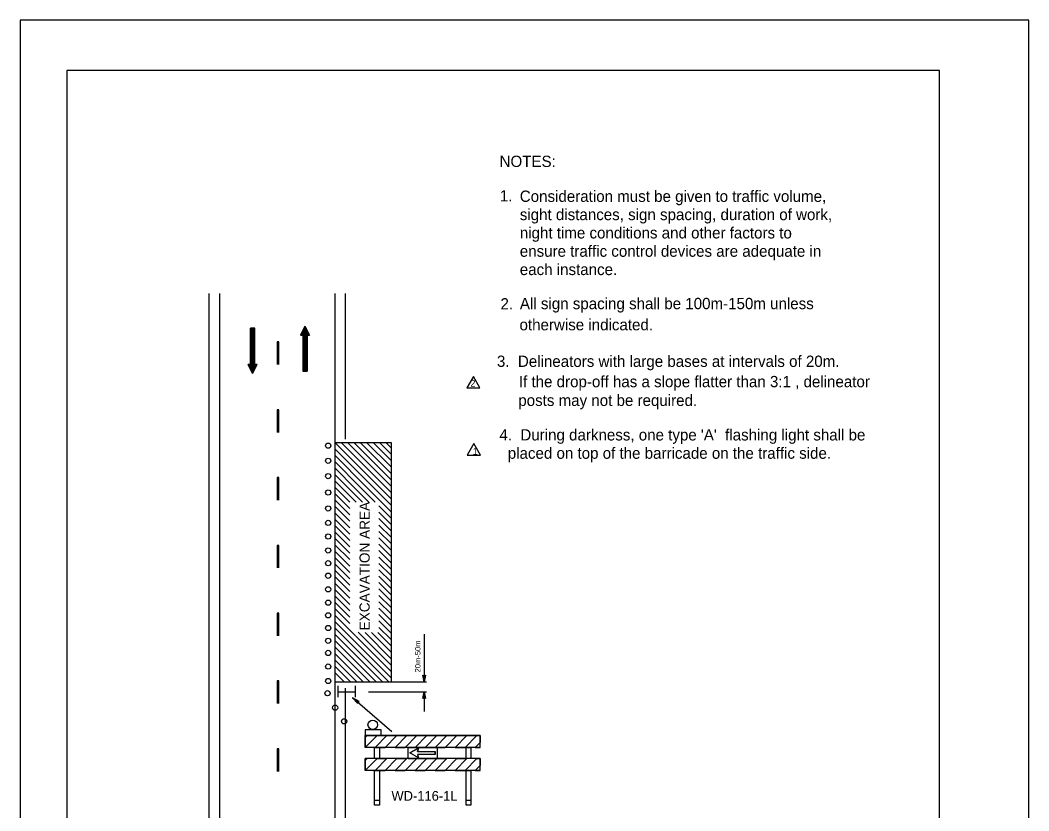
# Model space of a CAD drawing. Extents: x 1387 to 1603, y 134 to 413.
# Drawn here: x 1386.9 to 1602.9, y 243.5 to 412.8 of the extents above; entities that cross this region are included whole.
import ezdxf

# ---------------------------------------------------------------- set-up
doc = ezdxf.new("R2010")
doc.units = 0
for name, color, linetype in [('Level 1', 7, 'Continuous'), ('Level 10', 7, 'Continuous'), ('Level 2', 7, 'Continuous'), ('Level 3', 7, 'Continuous'), ('Level 5', 7, 'Continuous'), ('Level 60', 7, 'Continuous')]:
    doc.layers.add(name, color=color, linetype=linetype)

msp = doc.modelspace()

# ---------------------------------------------------------------- linework, layer by layer
at = {"layer": 'Level 1'}
msp.add_lwpolyline([(1484.02, 322.11), (1482.6, 319.64), (1485.43, 319.64)], close=True, dxfattribs=at)
msp.add_lwpolyline([(1458.06, 267.67), (1459.15, 266.47), (1459.11, 266.85), (1459.48, 266.89), (1458.06, 267.67), (1458.45, 267.37), (1459.04, 266.72), (1459.01, 266.92), (1459.21, 266.94), (1458.45, 267.37), (1458.83, 267.06), (1458.93, 266.94), (1458.93, 266.98), (1458.97, 266.99), (1458.83, 267.06), (1458.93, 266.98)], dxfattribs=at)
at = {"layer": 'Level 10'}
for p, q in [((1427.31, 354.27), (1427.31, 172.77)), ((1429.55, 354.27), (1429.55, 172.77)), ((1454.23, 354.27), (1454.23, 172.77)), ((1456.49, 354.27), (1456.49, 323.04)), ((1436.18, 339.07), (1436.18, 346.81)), ((1437.15, 346.81), (1436.18, 346.81)), ((1436.18, 338.1), (1436.18, 346.81)), ((1436.3, 337.86), (1436.3, 346.81)), ((1436.42, 337.62), (1436.42, 346.81)), ((1436.54, 337.38), (1436.54, 346.81)), ((1436.66, 337.14), (1436.66, 346.81)), ((1436.78, 337.38), (1436.78, 346.81)), ((1436.9, 337.62), (1436.9, 346.81)), ((1437.03, 337.86), (1437.03, 346.81)), ((1437.15, 339.07), (1437.15, 346.81)), ((1437.15, 338.1), (1437.15, 346.81)), ((1447.86, 347.27), (1446.89, 345.33)), ((1447.14, 345.82), (1447.14, 345.33)), ((1447.26, 346.06), (1447.26, 345.33)), ((1447.38, 346.3), (1447.38, 337.59)), ((1447.5, 346.54), (1447.5, 337.59)), ((1447.62, 346.79), (1447.62, 337.59)), ((1447.74, 347.03), (1447.74, 337.59)), ((1447.86, 347.27), (1447.86, 337.59)), ((1447.86, 347.27), (1448.83, 345.33)), ((1447.98, 347.03), (1447.98, 337.59)), ((1448.1, 346.79), (1448.1, 337.59)), ((1448.22, 346.54), (1448.22, 337.59)), ((1448.35, 346.3), (1448.35, 337.59)), ((1448.47, 346.06), (1448.47, 345.33)), ((1448.59, 345.82), (1448.59, 345.33)), ((1446.89, 345.33), (1447.38, 345.33)), ((1447.02, 345.58), (1447.02, 345.33)), ((1447.38, 345.33), (1447.38, 337.59)), ((1448.35, 345.33), (1448.35, 337.59)), ((1448.35, 345.33), (1448.83, 345.33)), ((1448.71, 345.58), (1448.71, 345.33)), ((1436.66, 337.14), (1435.69, 339.07)), ((1436.18, 339.07), (1435.69, 339.07)), ((1435.82, 338.83), (1435.82, 339.07)), ((1435.94, 338.59), (1435.94, 339.07)), ((1436.06, 338.35), (1436.06, 339.07)), ((1436.66, 337.14), (1437.63, 339.07)), ((1437.63, 339.07), (1437.15, 339.07)), ((1437.27, 338.35), (1437.27, 339.07)), ((1437.39, 338.59), (1437.39, 339.07)), ((1437.51, 338.83), (1437.51, 339.07)), ((1447.38, 337.59), (1448.35, 337.59)), ((1454.23, 322.35), (1466.32, 322.35)), ((1454.23, 322.35), (1466.32, 310.26)), ((1454.23, 322.35), (1466.32, 322.35)), ((1455.6, 322.35), (1466.32, 311.62)), ((1456.97, 322.35), (1466.32, 312.99)), ((1458.34, 322.35), (1466.32, 314.36)), ((1459.7, 322.35), (1466.32, 315.73)), ((1461.07, 322.35), (1466.32, 317.1)), ((1462.44, 322.35), (1466.32, 318.47)), ((1463.81, 322.35), (1466.32, 319.83)), ((1465.18, 322.35), (1466.32, 321.2)), ((1466.32, 322.35), (1466.32, 271.07)), ((1454.23, 320.98), (1466.32, 308.89)), ((1454.23, 319.61), (1460.98, 312.86)), ((1454.23, 318.25), (1459.61, 312.86)), ((1454.23, 316.88), (1458.67, 312.44)), ((1454.23, 315.51), (1458.67, 311.07)), ((1454.23, 314.14), (1458.81, 309.56)), ((1454.23, 312.77), (1457.44, 309.56)), ((1454.23, 311.4), (1457.44, 308.19)), ((1457.98, 311.75), (1460.19, 309.55)), ((1458.67, 312.44), (1461.55, 309.56)), ((1459.61, 312.86), (1462.91, 309.56)), ((1460.98, 312.86), (1466.32, 307.52)), ((1454.23, 310.04), (1457.44, 306.83)), ((1454.23, 308.67), (1457.44, 305.46)), ((1454.23, 307.3), (1457.44, 304.09)), ((1463.71, 308.76), (1466.32, 306.15)), ((1463.71, 307.4), (1466.32, 304.78)), ((1454.23, 305.93), (1457.44, 302.72)), ((1454.23, 304.56), (1457.44, 301.35)), ((1463.71, 306.03), (1466.32, 303.41)), ((1463.71, 304.66), (1466.32, 302.05)), ((1454.23, 303.19), (1457.44, 299.99)), ((1463.71, 303.29), (1466.32, 300.68)), ((1454.23, 301.82), (1457.44, 298.62)), ((1454.23, 300.46), (1457.44, 297.25)), ((1463.71, 301.92), (1466.32, 299.31)), ((1463.71, 300.55), (1466.32, 297.94)), ((1454.23, 299.09), (1454.24, 299.08)), ((1454.23, 299.09), (1457.44, 295.88)), ((1463.71, 299.19), (1466.32, 296.57)), ((1454.23, 297.72), (1457.44, 294.51)), ((1454.23, 296.35), (1457.44, 293.14)), ((1463.71, 297.82), (1466.32, 295.2)), ((1463.71, 296.45), (1466.32, 293.83)), ((1454.23, 294.98), (1457.44, 291.77)), ((1463.71, 295.08), (1466.32, 292.47)), ((1454.23, 293.62), (1457.44, 290.41)), ((1454.23, 292.25), (1457.44, 289.04)), ((1463.71, 293.71), (1466.32, 291.1)), ((1463.71, 292.34), (1466.32, 289.73)), ((1454.23, 290.88), (1457.44, 287.67)), ((1454.23, 289.51), (1457.44, 286.3)), ((1463.71, 290.98), (1466.32, 288.36)), ((1463.71, 289.61), (1466.32, 286.99)), ((1454.23, 288.14), (1457.44, 284.93)), ((1463.71, 288.24), (1466.32, 285.62)), ((1454.23, 286.77), (1457.44, 283.56)), ((1454.23, 285.4), (1457.44, 282.19)), ((1463.71, 286.87), (1466.32, 284.26)), ((1463.71, 285.5), (1466.32, 282.89)), ((1454.23, 284.04), (1458.67, 279.6)), ((1463.71, 284.13), (1466.32, 281.52)), ((1454.23, 282.67), (1458.67, 278.23)), ((1454.23, 281.3), (1464.46, 271.07)), ((1457.46, 282.18), (1458.67, 280.97)), ((1458.74, 280.9), (1466.32, 273.31)), ((1459.28, 281.72), (1466.32, 274.68)), ((1460.73, 281.64), (1466.32, 276.05)), ((1462.1, 281.64), (1466.32, 277.41)), ((1463.47, 281.64), (1466.32, 278.78)), ((1463.71, 282.76), (1466.32, 280.15)), ((1473.39, 281.27), (1473.39, 271.07)), ((1454.23, 279.93), (1463.09, 271.07)), ((1458.68, 279.59), (1466.32, 271.94)), ((1454.23, 278.56), (1461.72, 271.07)), ((1454.23, 277.19), (1460.36, 271.07)), ((1458.66, 278.24), (1465.83, 271.07)), ((1454.23, 275.82), (1458.99, 271.07)), ((1454.23, 274.46), (1457.62, 271.07)), ((1454.23, 273.09), (1456.25, 271.07)), ((1454.23, 271.07), (1466.32, 271.07)), ((1454.99, 267.79), (1454.99, 270.26)), ((1458.66, 267.79), (1458.66, 270.26)), ((1466.32, 271.07), (1473.87, 271.07)), ((1454.99, 268.98), (1458.66, 268.98)), ((1456.49, 269.76), (1456.49, 172.77)), ((1461.5, 268.98), (1465.17, 268.98)), ((1465.17, 268.98), (1473.87, 268.98)), ((1473.39, 268.98), (1473.39, 264.75)), ((1466.46, 260.38), (1458.06, 267.67))]:
    msp.add_line(p, q, dxfattribs=at)
for points in [[(1473.39, 271.07), (1473.09, 272.52), (1473.39, 272.28), (1473.69, 272.52)], [(1473.39, 268.98), (1473.69, 267.53), (1473.39, 267.77), (1473.09, 267.53)], [(1460.76, 259.57), (1464.15, 259.57), (1464.15, 260.8), (1460.76, 260.8)]]:
    msp.add_lwpolyline(points, close=True, dxfattribs=at)
for centre, radius in [((1452.85, 321.65), 0.558), ((1452.85, 318.42), 0.558), ((1452.85, 315.14), 0.558), ((1452.85, 311.63), 0.558), ((1452.85, 308.22), 0.558), ((1452.85, 305.12), 0.558), ((1452.85, 302.21), 0.558), ((1452.85, 299.23), 0.558), ((1452.85, 296.48), 0.558), ((1452.85, 293.81), 0.558), ((1452.85, 290.9), 0.558), ((1452.85, 288.05), 0.558), ((1452.85, 285.34), 0.558), ((1452.85, 282.61), 0.558), ((1452.85, 279.88), 0.558), ((1452.85, 277.28), 0.558), ((1452.85, 274.36), 0.558), ((1452.85, 271.26), 0.558), ((1452.71, 268.66), 0.558), ((1454.31, 265.56), 0.558), ((1456.26, 262.64), 0.558), ((1462.38, 261.9), 1.02)]:
    msp.add_circle(centre, radius, dxfattribs=at)
at = {"layer": 'Level 2'}
for p, q in [((1441.94, 343.86), (1441.94, 339.02)), ((1442.24, 343.86), (1441.94, 343.86)), ((1442.24, 339.02), (1442.24, 343.86)), ((1441.94, 329.34), (1441.94, 324.5)), ((1442.24, 329.34), (1441.94, 329.34)), ((1442.24, 324.5), (1442.24, 329.34)), ((1441.94, 314.83), (1441.94, 309.99)), ((1442.24, 314.83), (1441.94, 314.83)), ((1442.24, 309.99), (1442.24, 314.83)), ((1441.94, 300.31), (1441.94, 295.48)), ((1442.24, 300.31), (1441.94, 300.31)), ((1442.24, 295.48), (1442.24, 300.31)), ((1441.94, 285.8), (1441.94, 280.96)), ((1442.24, 285.8), (1441.94, 285.8)), ((1442.24, 280.96), (1442.24, 285.8)), ((1441.94, 271.29), (1441.94, 266.45)), ((1442.24, 271.29), (1441.94, 271.29)), ((1442.24, 266.45), (1442.24, 271.29)), ((1460.65, 271.64), (1460.65, 271.64)), ((1441.94, 256.77), (1441.94, 251.93)), ((1442.24, 256.77), (1441.94, 256.77)), ((1442.24, 251.93), (1442.24, 256.77))]:
    msp.add_line(p, q, dxfattribs=at)
at = {"layer": 'Level 3'}
msp.add_line((1460.97, 271.66), (1460.97, 271.66), dxfattribs=at)
at = {"layer": 'Level 5'}
for p, q in [((1485.37, 259.57), (1460.76, 259.57)), ((1460.76, 257.05), (1460.76, 259.57)), ((1460.76, 259.57), (1485.37, 259.57)), ((1462.78, 259.57), (1463.29, 259.57)), ((1481.34, 259.57), (1480.33, 259.57)), ((1485.37, 257.05), (1485.37, 259.57)), ((1485.37, 257.05), (1460.76, 257.05)), ((1462.78, 257), (1462.78, 257.05)), ((1482.35, 257), (1482.35, 257.05)), ((1469.94, 257.02), (1476.15, 257.02)), ((1469.94, 257.02), (1476.15, 257.02)), ((1469.94, 254.7), (1469.94, 257.02)), ((1469.94, 257.02), (1476.15, 257.02)), ((1469.94, 254.7), (1469.94, 257.02)), ((1469.94, 257.02), (1476.15, 257.02)), ((1472.16, 256.9), (1470.35, 255.86)), ((1472.16, 256.9), (1470.35, 255.86)), ((1470.35, 255.86), (1472.16, 256.9)), ((1472.16, 254.82), (1470.35, 255.86)), ((1472.16, 254.82), (1470.35, 255.86)), ((1471.96, 256.19), (1472.16, 256.9)), ((1471.96, 256.19), (1472.16, 256.9)), ((1472.16, 256.9), (1471.96, 256.19)), ((1471.96, 256.19), (1475.74, 256.19)), ((1475.74, 255.53), (1471.96, 255.53)), ((1471.96, 255.53), (1472.16, 254.82)), ((1475.74, 255.53), (1471.96, 255.53)), ((1471.96, 255.53), (1472.16, 254.82)), ((1475.74, 255.53), (1475.74, 256.19)), ((1475.74, 255.53), (1475.74, 256.19)), ((1475.74, 256.19), (1475.74, 255.53)), ((1476.15, 257.02), (1476.15, 254.7)), ((1476.15, 257.02), (1476.15, 254.7)), ((1460.76, 252.13), (1460.76, 254.66)), ((1485.37, 254.66), (1460.76, 254.66)), ((1476.15, 254.7), (1469.94, 254.7)), ((1476.15, 254.7), (1469.94, 254.7)), ((1469.94, 254.7), (1476.15, 254.7)), ((1476.15, 254.7), (1469.94, 254.7)), ((1483.36, 254.66), (1482.85, 254.66)), ((1485.37, 252.13), (1485.37, 254.66)), ((1485.37, 252.13), (1460.76, 252.13)), ((1463.79, 245.7), (1462.78, 245.7)), ((1483.36, 245.7), (1482.35, 245.7))]:
    msp.add_line(p, q, dxfattribs=at)
for points in [[(1460.76, 257.05), (1463.29, 259.57), (1461.15, 259.57), (1460.76, 259.19), (1460.76, 257.05)], [(1465.04, 257.05), (1467.56, 259.57), (1465.42, 259.57), (1462.9, 257.05), (1465.04, 257.05)], [(1469.32, 257.05), (1471.84, 259.57), (1469.7, 259.57), (1467.18, 257.05), (1469.32, 257.05)], [(1473.6, 257.05), (1476.12, 259.57), (1473.98, 259.57), (1471.46, 257.05), (1473.6, 257.05)], [(1480.4, 259.57), (1478.26, 259.57), (1475.74, 257.05), (1477.88, 257.05), (1480.4, 259.57)], [(1484.68, 259.57), (1482.54, 259.57), (1480.02, 257.05), (1482.16, 257.05), (1484.68, 259.57)], [(1485.37, 258.12), (1484.3, 257.05), (1485.37, 257.05), (1485.37, 258.12)], [(1460.76, 252.13), (1463.29, 254.66), (1461.15, 254.66), (1460.76, 254.27), (1460.76, 252.13)], [(1465.04, 252.13), (1467.56, 254.66), (1465.42, 254.66), (1462.9, 252.13), (1465.04, 252.13)], [(1469.32, 252.13), (1471.84, 254.66), (1469.7, 254.66), (1467.18, 252.13), (1469.32, 252.13)], [(1473.6, 252.13), (1476.12, 254.66), (1473.98, 254.66), (1471.46, 252.13), (1473.6, 252.13)], [(1480.4, 254.66), (1478.26, 254.66), (1475.74, 252.13), (1477.88, 252.13), (1480.4, 254.66)], [(1484.68, 254.66), (1482.54, 254.66), (1480.02, 252.13), (1482.16, 252.13), (1484.68, 254.66)], [(1485.37, 253.21), (1484.3, 252.13), (1485.37, 252.13), (1485.37, 253.21)]]:
    msp.add_lwpolyline(points, dxfattribs=at)
for points in [[(1463.29, 259.57), (1465.42, 259.57), (1462.9, 257.05), (1460.76, 257.05)], [(1461.15, 259.57), (1460.76, 259.57), (1460.76, 259.19)], [(1467.56, 259.57), (1469.7, 259.57), (1467.18, 257.05), (1465.04, 257.05)], [(1471.84, 259.57), (1473.98, 259.57), (1471.46, 257.05), (1469.32, 257.05)], [(1476.12, 259.57), (1478.26, 259.57), (1475.74, 257.05), (1473.6, 257.05)], [(1480.4, 259.57), (1482.54, 259.57), (1480.02, 257.05), (1477.88, 257.05)], [(1484.68, 259.57), (1485.37, 259.57), (1485.37, 258.12), (1484.3, 257.05), (1482.16, 257.05)], [(1462.78, 257), (1463.79, 257.05), (1463.79, 254.66), (1462.78, 254.66)], [(1482.35, 257), (1483.36, 257), (1483.36, 254.66), (1482.35, 254.66)], [(1460.76, 254.66), (1461.15, 254.66), (1460.76, 254.27)], [(1463.29, 254.66), (1465.42, 254.66), (1462.9, 252.13), (1460.76, 252.13)], [(1467.56, 254.66), (1469.7, 254.66), (1467.18, 252.13), (1465.04, 252.13)], [(1471.84, 254.66), (1473.98, 254.66), (1471.46, 252.13), (1469.32, 252.13)], [(1476.12, 254.66), (1478.26, 254.66), (1475.74, 252.13), (1473.6, 252.13)], [(1480.4, 254.66), (1482.54, 254.66), (1480.02, 252.13), (1477.88, 252.13)], [(1484.68, 254.66), (1485.37, 254.66), (1485.37, 253.21), (1484.3, 252.13), (1482.16, 252.13)], [(1462.78, 252.11), (1463.79, 252.11), (1463.79, 244.69), (1462.78, 244.69)], [(1482.35, 252.11), (1483.36, 252.11), (1483.36, 244.69), (1482.35, 244.69)]]:
    msp.add_lwpolyline(points, close=True, dxfattribs=at)
at = {"layer": 'Level 60'}
msp.add_line((1602.88, 412.75), (1602.88, 412.75), dxfattribs=at)
for points in [[(1602.88, 412.75), (1386.88, 412.75), (1386.88, 133.75), (1602.88, 133.75)], [(1583.75, 401.95), (1396.88, 401.95), (1396.88, 144.56), (1583.75, 144.56)]]:
    msp.add_lwpolyline(points, close=True, dxfattribs=at)
for points in [[(1483.92, 336.49), (1482.53, 334.07)], [(1485.31, 334.07), (1483.92, 336.49)], [(1482.53, 334.07), (1482.5, 334.02), (1485.34, 334.02), (1485.31, 334.07)]]:
    msp.add_lwpolyline(points, dxfattribs=at)

# ---------------------------------------------------------------- texts
at = {"layer": 'Level 1'}
msp.add_text('1', height=1.45, rotation=360, dxfattribs=at).set_placement((1483.79, 319.7))
at = {"layer": 'Level 10'}
for s, p in [('NOTES:', (1489.54, 381.32)), ('1.', (1489.6, 373.94)), ('Consideration must be given to traffic volume,', (1493.87, 373.85)), ('sight distances, sign spacing, duration of work,', (1493.87, 369.94)), ('night time conditions and other factors to', (1493.87, 366.02)), ('ensure traffic control devices are adequate in', (1493.87, 362.1)), ('each instance.', (1493.87, 358.18)), ('2.', (1489.73, 350.82)), ('All sign spacing shall be 100m-150m unless', (1493.89, 350.88)), ('otherwise indicated.', (1493.81, 346.35)), ('3.  Delineators with large bases at intervals of 20m. ', (1488.97, 338.52)), ('If the drop-off has a slope flatter than 3:1 , delineator', (1493.67, 334.17)), ('posts may not be required.', (1493.55, 330.16)), ("4.  During darkness, one type 'A'  flashing light shall be ", (1489.5, 322.77)), ('  placed on top of the barricade on the traffic side.', (1489.5, 318.85))]:
    msp.add_text(s, height=2.419, dxfattribs=at).set_placement(p)
for s, height, rotation, p in [('EXCAVATION AREA', 2.1776, 90, (1461.72, 282.11)), ('20m-50m', 1.171, 90, (1472.6, 273.11)), ('WD-116-1L', 2.068, 360, (1466.39, 245.64))]:
    msp.add_text(s, height=height, rotation=rotation, dxfattribs=at).set_placement(p)
at = {"layer": 'Level 60'}
msp.add_text('2', height=1.45, rotation=360, dxfattribs=at).set_placement((1483.29, 334.29))

doc.saveas('drawing.dxf')
